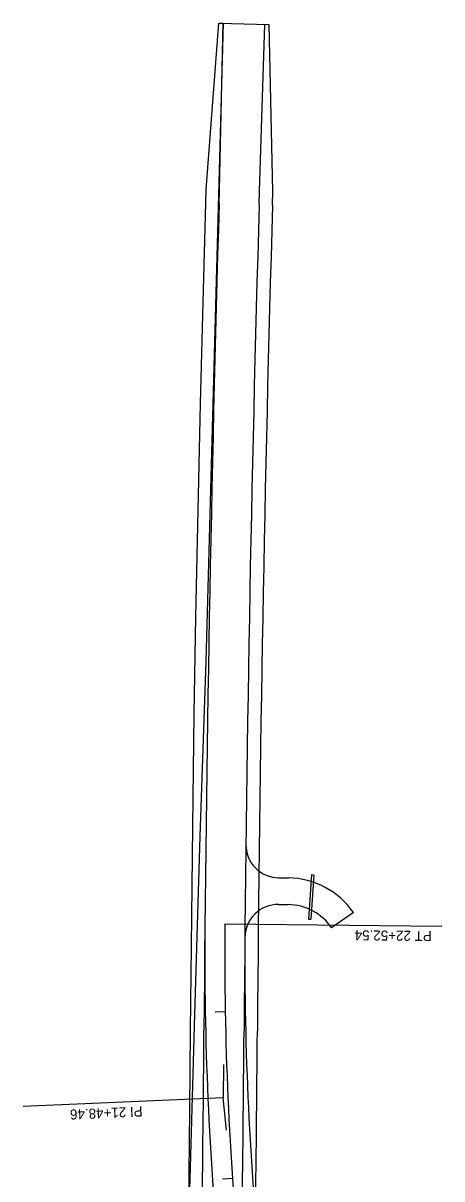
# Model space of a CAD drawing. Extents: x 1445610 to 1446352, y 2042797 to 2056486.
# Drawn here: x 1446000 to 1446251, y 2044604 to 2045297 of the extents above; entities that cross this region are included whole.
import ezdxf

# ---------------------------------------------------------------- set-up
doc = ezdxf.new("R2010")
doc.units = 0
for name, color, linetype in [('20', 7, 'Continuous'), ('Level 43', 7, 'Continuous'), ('R_Horz Alg', 7, 'Continuous'), ('R_Horz Alg Annot', 7, 'Continuous'), ('R_Horz Alg Stationing', 7, 'Continuous'), ('R_Proposed Road', 7, 'Continuous')]:
    doc.layers.add(name, color=color, linetype=linetype)

msp = doc.modelspace()

# ---------------------------------------------------------------- linework, layer by layer
at = {"layer": '20'}
msp.add_lwpolyline([(1446099.19, 2044587.77), (1446099.81, 2044645.31), (1446100.22, 2044692.73), (1446100.65, 2044743.22), (1446101.46, 2044815.39), (1446102.41, 2044882.46), (1446103.41, 2044940.88), (1446106.1, 2045068.66), (1446107.43, 2045122.08), (1446109.28, 2045188.98), (1446109.28, 2045188.98), (1446109.52, 2045197.16), (1446117.13, 2045296.98), (1446119.67, 2045296.9), (1446109.26, 2044914.17), (1446105.78, 2044809.37), (1446102.6, 2044702.27), (1446099.67, 2044603.66)], close=True, dxfattribs=at)
at = {"layer": 'Level 43'}
for p, q in [((1446172.58, 2044786.06), (1446170.81, 2044759.6)), ((1446174.08, 2044785.96), (1446172.31, 2044759.5)), ((1446174.08, 2044785.96), (1446172.58, 2044786.06)), ((1446170.81, 2044759.6), (1446172.31, 2044759.5))]:
    msp.add_line(p, q, dxfattribs=at)
at = {"layer": 'R_Horz Alg'}
msp.add_arc((1448030.54, 2044737.1), 1909.86, 179.41289, 185.66397, dxfattribs=at)
at = {"layer": 'R_Horz Alg Annot'}
for p in [(1446119.92, 2044672.29), (1446121.64, 2044632.94)]:
    msp.add_line(p, (1446119.71, 2044652.39), dxfattribs=at)
for points in [[(1446120.78, 2044756.67), (1446250.78, 2044755.34)], [(1446119.71, 2044652.39), (1445999.83, 2044647.07)]]:
    msp.add_lwpolyline(points, dxfattribs=at)
at = {"layer": 'R_Horz Alg Stationing'}
for points in [[(1446114.97, 2044704.02), (1446120.97, 2044704.13)], [(1446119.32, 2044603.82), (1446125.31, 2044604.23)]]:
    msp.add_lwpolyline(points, dxfattribs=at)
at = {"layer": 'R_Proposed Road'}
for p, q in [((1446117.52, 2045196.92), (1446119.67, 2045296.9)), ((1446141.51, 2045196.23), (1446144.62, 2045296.18)), ((1446149.5, 2045195.99), (1446147.24, 2045296.1)), ((1446117.28, 2045188.75), (1446117.52, 2045196.92)), ((1446141.27, 2045188.05), (1446141.51, 2045196.23)), ((1446149.27, 2045187.82), (1446149.5, 2045195.99)), ((1446153.1, 2044784.31), (1446158.81, 2044784.25)), ((1446152.92, 2044768.31), (1446158.63, 2044768.25)), ((1446197.82, 2044763.46), (1446184.64, 2044754.39))]:
    msp.add_line(p, q, dxfattribs=at)
msp.add_lwpolyline([(1446117.13, 2045296.98), (1446147.24, 2045296.1)], dxfattribs=at)
for centre, radius, start, end in [((1469037.89, 2044521.83), 22930.31, 178.333333, 179.573112), ((1469037.89, 2044521.83), 22906.31, 178.333333, 179.573112), ((1469037.89, 2044521.83), 22898.31, 178.333333, 179.573112), ((1446153.32, 2044804.31), 20, 179.29279, 269.36289), ((1446158.28, 2044736.25), 48, 34.53575, 89.36289), ((1446152.7, 2044748.31), 20, 89.36289, 179.43299), ((1446158.28, 2044736.25), 32, 34.53575, 89.36289), ((1448030.54, 2044737.1), 1921.86, 179.41289, 185.66397), ((1448030.54, 2044737.1), 1897.86, 179.41289, 185.66397), ((1423202.54, 2044863.34), 22906.31, 358.983333, 359.573112), ((1423202.54, 2044863.34), 22930.31, 358.983333, 359.573112), ((1423202.54, 2044863.34), 22938.31, 358.983333, 359.573112)]:
    msp.add_arc(centre, radius, start, end, dxfattribs=at)

# ---------------------------------------------------------------- texts
at = {"layer": 'R_Horz Alg Annot'}
for s, rotation, p in [('PT 22+52.54', 179.41289, (1446244.75, 2044752.4)), ('PI 21+48.46', 182.53843, (1446071.27, 2044647.23))]:
    msp.add_text(s, height=6, rotation=rotation, dxfattribs=at).set_placement(p)

doc.saveas('drawing.dxf')
